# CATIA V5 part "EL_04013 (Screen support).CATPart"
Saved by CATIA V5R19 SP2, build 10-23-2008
Part number: ecran_support
Bounding box of the stored display mesh (mm): x -20.791 to 1.956, y -98.231 to 0, z -15 to 126
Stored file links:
  C:\Users\thoma\Desktop\EPSA\ELIZ-2021\EL_Electrical\CATIA\EL_A0100 (Dash Panel)\EL_04013 (Screen support).CATPart
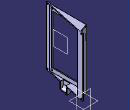
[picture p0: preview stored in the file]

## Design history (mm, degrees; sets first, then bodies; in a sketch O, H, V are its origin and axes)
Body1 (main body)
  Sketch1 on xy-plane, origin (0, 0, 0), H (1, 0, 0), V (0, 1, 0)
    line L1 (1.9563, -0.4158) -> (-18.8349, -98.2306)
    line L2 (-1.2475, -5.8689) -> (-19.5437, -11.9459)
    point P4 (-19.5437, -11.9459)
    point P5 (-76.5266, -97.0821)
    line L3 (-19.5437, -91.9459) -> (-19.5437, -11.9459)
    point P7 (-19.5437, -11.9459)
    line L4 (-1.2475, -5.8689) -> (0, 0)
    point P8 (0, 0)
    line L5 (0, 0) -> (1.9563, -0.4158)
    line L6 (-19.5437, -91.9459) -> (-20.7912, -97.8148)
    line L7 (-18.8349, -98.2306) -> (-20.7912, -97.8148)
    length L3 = 80
    angle L3 L1 = 12
    length L1 = 100
    distance L4 L6 = 0
    length L7 = 2
    length L4 = 6
    length L6 = 6
    coincidence: P7 L2, P4 P7, P8 O
    vertical: L3 V
    parallelism: L4 L1
    perpendicularity: L5 L4, L7 L1
  Pad1: profile Sketch1, direction (0, 0, 1), length 126
  Sketch2 on face of Pad1 from Sketch1.L3, origin (-19.5437, 0, 0), H (0, -1, 0), V (0, 0, 1)
    line L1 (18.1459, 115.85) -> (85.7459, 115.85)
    line L2 (85.7459, 115.85) -> (85.7459, 10.15)
    line L3 (85.7459, 10.15) -> (18.1459, 10.15)
    line L4 (18.1459, 10.15) -> (18.1459, 115.85)
    reference projected line E1 (91.9459, 0) -> (91.9459, 124) from edge [face of Pad1 from Sketch1.L6 | face of Pad1 from Sketch1.L3]
    circle A1 centre (85.7459, 119.8) radius 1.6
    point P5 (85.7459, 119.8)
    circle A2 centre (18.1459, 119.8) radius 1.6
    point P6 (18.1459, 119.8)
    circle A3 centre (85.7459, 6.2) radius 1.6
    point P7 (85.7459, 6.2)
    circle A4 centre (18.1459, 6.2) radius 1.6
    point P8 (18.1459, 6.2)
    construction line L5 (18.1459, 6.2) -> (85.7459, 6.2)
    axis line L6 (85.7459, 119.8) -> (18.1459, 119.8)
    reference projected line E2 (11.9459, 126) -> (91.9459, 126) from edge [face of Pad1 from Sketch1.L3 | end face of Pad1]
    length L2 = 105.7
    length L1 = 67.6
    distance L2 E1 = 6.2
    radius A2 = 1.6
    radius A1 = 1.6
    radius A3 = 1.6
    radius A4 = 1.6
    distance L5 L3 = 3.95
    distance L6 L1 = 3.95
    distance L6 E2 = 6.2
    horizontal: L1 H, L3 H, L5 H, L6 H
    vertical: L2 V, L4 V
    coincidence: P5 L2, P6 L4, P7 L2, P8 L4
  Pocket1: profile Sketch2, direction (1, 0, 0), through (limit type 6)
  Plane1: type Offset, RefPlane face of Pad1 from Sketch1.L3, Offset 2
  Sketch3 on Plane1, origin (-17.5437, 0, 0), H (0, 1, 0), V (0, 0, 1)
    line L1 (-90.9459, 124.1) -> (-13.9459, 124.1)
    line L2 (-13.9459, 124.1) -> (-13.9459, 2.1)
    line L3 (-13.9459, 2.1) -> (-90.9459, 2.1)
    line L4 (-90.9459, 2.1) -> (-90.9459, 124.1)
    reference projected line E1 (-18.1459, 115.85) -> (-85.7459, 115.85) from edge [face of Pad1 from Sketch1.L1 | face of Pocket1 from Sketch2.L1]
    reference projected line E2 (-85.7459, 9.5) -> (-85.7459, 114.5) from edge [face of Pocket1 from Sketch2.L2 | face of Pad1 from Sketch1.L1]
    length L1 = 77
    length L2 = 122
    distance E1 L1 = 8.25
    distance E2 L4 = 5.2
    horizontal: L1 H, L3 H
    vertical: L2 V, L4 V
  Pocket2: profile Sketch3, direction (1, 0, 0), through (limit type 6)
  Fillet1: radius 1, on edge [face of Pad1 from Sketch1.L2 | face of Pad1 from Sketch1.L4]; edge [face of Pad1 from Sketch1.L6 | face of Pad1 from Sketch1.L3]; edge [face of Pad1 from Sketch1.L3 | face of Pad1 from Sketch1.L2]; edge [face of Pad1 from Sketch1.L3 | end face of Pad1]; edge [start face of Pad1 | face of Pad1 from Sketch1.L3]; edge [face of Pad1 from Sketch1.L2 | end face of Pad1]; edge [start face of Pad1 | face of Pad1 from Sketch1.L2]
  Sketch4 on face of Pad1 from Sketch1.L4, origin (0, 0, 0), H (-0.2079, -0.9781, 0), V (0, 0, 1)
    circle A1 centre (3, 123) radius 1.6
    circle A2 centre (97, 123) radius 1.6
    circle A3 centre (97, 3) radius 1.6
    circle A4 centre (3, 3) radius 1.6
    construction line L1 (97, 3) -> (3, 3)
    construction line L2 (97, 3) -> (97, 123)
    construction line L3 (97, 123) -> (3, 123)
    axis line L4 (3, 123) -> (3, 3)
    reference projected line E1 (0, 0) -> (0, 124) from edge [face of Pad1 from Sketch1.L4 | face of Pad1 from Sketch1.L5]
    reference projected line E2 (100, 0) -> (100, 124) from edge [face of Pad1 from Sketch1.L7 | face of Pad1 from Sketch1.L6]
    reference projected line E3 (0, 126) -> (6, 126) from edge [face of Pad1 from Sketch1.L4 | end face of Pad1]
    radius A2 = 1.6
    radius A3 = 1.6
    radius A4 = 1.6
    radius A1 = 1.6
    distance L4 E1 = 3
    distance L2 E2 = 3
    distance L1 H = 3
    distance L3 E3 = 3
    horizontal: L1 H, L3 H
    vertical: L2 V, L4 V
  Pocket3: profile Sketch4, direction (0.9781, -0.2079, 0), through (limit type 3)
  DatumCurve1 to DatumCurve5
  Sketch5 on face of Pocket2 from Sketch3.L3, origin (0, 0, 2.1), H (1, 0, 0), V (0, 1, 0)
    line L1 (-15.9437, -44.3459) -> (-7.3813, -44.3459)
    line L2 (-7.3813, -44.3459) -> (-7.3813, -59.4659)
    line L3 (-7.3813, -59.4659) -> (-15.9437, -59.4659)
    line L4 (-15.9437, -59.4659) -> (-15.9437, -44.3459)
    point P2 (-7.3813, -44.3459)
    reference projected line E1 (-15.9437, -44.3459) -> (-15.9437, -59.4659) from edge of DatumCurve2
    reference projected line E2 (-15.9437, -59.4659) -> (-9.9437, -59.4659) from edge of DatumCurve4
    reference projected line E3 (-15.9437, -44.3459) -> (-9.9437, -44.3459) from edge of DatumCurve5
    reference projected line E4 (-0.915, -13.924) -> (-17.0693, -89.9242) from edge of DatumCurve10
    horizontal: L1 H, L3 H
    vertical: L2 V, L4 V
    coincidence: E1 L4, E2 L3, L1 E3, P2 E4
  Pocket4: profile Sketch5, direction (0, 0, -1), through (limit type 6)
  Sketch6 on start face of Pad1, origin (0, 0, 0), H (1, 0, 0), V (0, -1, 0)
    line L1 (-6.9562, 42.3459) -> (-17.9437, 42.3459)
    line L2 (-17.9437, 42.3459) -> (-17.9437, 61.4659)
    line L3 (-17.9437, 61.4659) -> (-11.0203, 61.4659)
    line L4 (-6.9562, 42.3459) -> (-11.0203, 61.4659)
    reference projected line E1 (-18.8349, 98.2306) -> (1.9563, 0.4158) from edge [start face of Pad1 | face of Pad1 from Sketch1.L1]
    reference projected line E2 (-15.9437, 44.3459) -> (-7.3813, 44.3459) from edge [start face of Pad1 | face of Pocket4 from Sketch5.L1]
    reference projected line E3 (-15.9437, 44.3459) -> (-15.9437, 59.4659) from edge [face of Pocket4 from Sketch5.L4 | start face of Pad1]
    reference projected line E4 (-10.5952, 59.4659) -> (-15.9437, 59.4659) from edge [start face of Pad1 | face of Pocket4 from Sketch5.L3]
    distance L1 E2 = 2
    distance L2 E3 = 2
    distance L3 E4 = 2
    horizontal: L1 H, L3 H
    vertical: L2 V
    coincidence: L4 E1
  Pad2: profile Sketch6, direction (0, 0, -1), length 15
  Sketch7 on start face of Pad2, origin (0, 0, 0), H (1, 0, 0), V (0, 1, 0)
    line L1 (-15.9437, -44.3459) -> (-0.9437, -44.3459)
    line L2 (-0.9437, -44.3459) -> (-0.9437, -59.4659)
    line L3 (-0.9437, -59.4659) -> (-15.9437, -59.4659)
    line L4 (-15.9437, -59.4659) -> (-15.9437, -44.3459)
    reference projected line E3 (-15.9437, -44.3459) -> (-15.9437, -59.4659) from edge [face of Pocket4 from Sketch5.L4 | start face of Pad2]
    reference projected line E4 (-15.9437, -44.3459) -> (-7.3813, -44.3459) from edge [start face of Pad2 | face of Pocket4 from Sketch5.L1]
    reference projected line E5 (-10.5952, -59.4659) -> (-15.9437, -59.4659) from edge [start face of Pad2 | face of Pocket4 from Sketch5.L3]
    distance L4 E3 = 0
    length L1 = 15
    horizontal: L1 H, L3 H
    vertical: L2 V, L4 V
    coincidence: E4 L1, L3 E5
  Pocket5: profile Sketch7, direction (0, 0, -1), length 13
  Fillet2: radius 6.5, on edge [face of Pad2 from Sketch6.L2 | end face of Pad2]; edge [face of Pocket5 | end face of Pocket5]
  Fillet3: radius 1, on edge [face of Pad2 from Sketch6.L2 | face of Pad2 from Sketch6.L3]; edge [face of Pad2 from Sketch6.L3 | face of Fillet2]; edge [face of Pad2 from Sketch6.L3 | end face of Pad2]; edge [face of Pad2 from Sketch6.L1 | face of Pad2 from Sketch6.L2]; edge [face of Pad2 from Sketch6.L1 | face of Fillet2]; edge [face of Pad2 from Sketch6.L1 | end face of Pad2]
  DatumCurve6 to DatumCurve9
  Sketch8 on face of Pocket2 from Sketch3.L2, origin (0, -13.9459, 0), H (1, 0, 0), V (0, 0, 1)
    line L1 (-15.4437, 112.15) -> (-12.7437, 112.15)
    line L2 (-12.7437, 112.15) -> (-12.7437, 99.15)
    line L3 (-12.7437, 99.15) -> (-15.4437, 99.15)
    line L4 (-15.4437, 99.15) -> (-15.4437, 112.15)
    reference projected line E1 (-15.9437, 99.15) -> (-13.2437, 99.15) from edge of DatumCurve8
    reference projected line E2 (-13.2437, 99.15) -> (-13.2437, 113.15) from edge of DatumCurve11
    reference projected line E3 (-15.9437, 113.15) -> (-13.2437, 113.15) from edge of DatumCurve12
    length L3 = 2.7
    distance L2 E2 = 0.5
    distance L1 E3 = 1
    horizontal: L1 H, L3 H
    vertical: L2 V, L4 V
    coincidence: E1 L3
  Pocket6: profile Sketch8, direction (0, 1, 0), length 3
  DatumCurve10 to DatumCurve12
